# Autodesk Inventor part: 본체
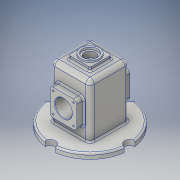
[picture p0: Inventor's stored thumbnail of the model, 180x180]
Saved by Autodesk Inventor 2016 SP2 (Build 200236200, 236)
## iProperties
Created: 2018-07
Part Number: 본체
Material: 알루미늄 6061
Document SubType Name: Modeling
Designer: Administrator
Density: 2.7 g/cm^3
Appearance: 알루미늄 - 평지
Mass: 905.953 g
Surface Area: 1026.21 cm^2
Volume: 335.538 cm^3
Author: Administrator
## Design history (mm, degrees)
sketch "스케치11"
  geometry: L1 (-37, -37)-(37, -37); L2 (37, -37)-(37, 37); L3 (37, 37)-(-37, 37); L4 (-37, 37)-(-37, -37); L5 (-37, -37)-(37, 37); L6 (37, -37)-(-37, 37); 1 further point
  constraints: 12 end point, 2 midpoint, 2 parallel, 1 horizontal, 1 perpendicular
  dimensions: "d36" = 74 distance of L3.end L2.end; "d37" = 74 distance of L2.end L1.end
extrude "돌출9" new body sketch "스케치11" distance "d38" = 100; taper "d39" = 0 deg
feature "쉘2" dims "d40" = 5
sketch "스케치12"
  geometry: L1 (20, -20)-(-20, -20); L2 (-20, -20)-(-20, 20); L3 (-20, 20)-(20, 20); L4 (20, 20)-(20, -20); L5 (20, -20)-(-20, 20); L6 (-20, -20)-(20, 20); 1 further point
  constraints: 12 end point, 2 midpoint, 2 parallel, 1 horizontal, 1 perpendicular
  dimensions: "d41" = 40 distance of L2.end L3.end; "d42" = 40 distance of L1.end L2.end
extrude "돌출10" join sketch "스케치12" distance "d43" = 7; taper "d44" = 0 deg
sketch "스케치14"
  geometry: A1 r 75 centre (0, 0) between (74.333, 9.978) and (9.978, 74.333); A2 r 10 centre (75, 0) between (74.333, -9.978) and (74.333, 9.978); A3 r 10 centre (0, -75) between (-9.978, -74.333) and (9.978, -74.333); A4 r 10 centre (-75, 0) between (-74.333, -9.978) and (-74.333, 9.978); A5 r 10 centre (0, 75) between (-9.978, 74.333) and (9.978, 74.333); A6 r 75 centre (0, 0) between (74.333, -9.978) and (74.333, 9.978); A7 r 75 centre (0, 0) between (-9.978, -74.333) and (9.978, -74.333); A8 r 75 centre (0, 0) between (9.978, -74.333) and (74.333, -9.978); A9 r 75 centre (0, 0) between (-74.333, -9.978) and (-9.978, -74.333); A10 r 75 centre (0, 0) between (-74.333, 9.978) and (-74.333, -9.978); A11 r 75 centre (0, 0) between (-9.978, 74.333) and (-74.333, 9.978); A12 r 75 centre (0, 0) between (9.978, 74.333) and (-9.978, 74.333); 1 further point
  constraints: 38 point on circle, 12 centre point, 2 horizontal alignment, 2 vertical alignment, 1 coincident
  dimensions: "d48" = 150 diameter of A1; "d49" = 20 diameter of A2; "d50" = 20 diameter of A3; "d51" = 20 diameter of A4; "d52" = 20 diameter of A5
extrude "돌출12" join sketch "스케치14" distance "d53" = 10; taper "d54" = 0 deg
sketch "스케치15"
  geometry: L1 (-37.333, -110)-(27.022, -110) reference; L2 (62, -30)-(12, -30); L3 (12, -30)-(12, -80); L4 (12, -80)-(62, -80); L5 (62, -80)-(62, -30); L6 (62, -30)-(12, -80); L7 (12, -30)-(62, -80); 2 further points
  constraints: 12 end point, 2 midpoint, 2 parallel, 1 horizontal, 1 perpendicular, 1 vertical alignment
  dimensions: "d55" = 50 distance of L4.end L3.end; "d56" = 50 distance of L3.end L2.end; "d57" = 55 distance from line of L1 point (37, -55)
extrude "돌출13" join sketch "스케치15" distance "d58" = 13; taper "d59" = 0 deg
sketch "스케치16"
  geometry: L1 (-37.333, -110)-(27.022, -110) reference; L2 (62, -30)-(12, -30); L3 (12, -30)-(12, -80); L4 (12, -80)-(62, -80); L5 (62, -80)-(62, -30); L6 (62, -30)-(12, -80); L7 (12, -30)-(62, -80); 3 further points
  constraints: 12 end point, 3 midpoint, 2 parallel, 1 horizontal, 1 perpendicular, 1 vertical alignment
  dimensions: "d60" = 50 distance of L4.end L3.end; "d61" = 50 distance of L3.end L2.end; "d62" = 55 distance from line of L1 point (37, -55)
extrude "돌출14" join sketch "스케치16" distance "d63" = 13; taper "d64" = 0 deg
sketch "스케치17"
  geometry: L1 (70, 37)-(70, 50) reference; L2 (5, 32)-(95, 32) reference; L3 (70, -37)-(70, -50) reference; L4 (5, -32)-(95, -32) reference; L5 (70, 50)-(20, 50) reference; L6 (20, -50)-(70, -50) reference; L7 (45, 32)-(45, -32); L8 (0, -9.978)-(0, -74.333) reference; L9 (0, -74.333)-(-10, -74.333) reference; L10 (-10, -9.978)-(-10, -74.333) reference; L11 (0, -9.978)-(-10, -9.978) reference; L12 (45, 32)-(70, 32); L13 (70, 32)-(67.452, 25); L14 (67.452, 25)-(45, 25); L15 (45, 32)-(45, 25); 1 further point
  constraints: 10 end point, 4 point on line, 2 perpendicular, 1 collinear, 1 vertical alignment
  dimensions: "d68" = 55 distance between parallel lines of L10 L7; "d69" = 7 vertical distance of L13.end L12.end; "d70" = 110 deg angle of L2 L13
revolve "회전1" sketch "스케치17" stored, may be unused: angle "d71" = 90 deg
sketch "스케치18"
  geometry: L1 (-37.333, -110)-(27.022, -110) reference; C1 r 16 at (37, -55); 1 further point
  constraints: 1 centre point, 1 vertical alignment
  dimensions: "d72" = 32 diameter of C1; "d73" = 55 distance from line of L1 C1.centre
extrude "돌출15" cut sketch "스케치18" stored distance "d74" = 13; taper "d75" = 0 deg
sketch "스케치19"
  geometry: L1 (32, 32)-(-32, 32); L2 (-32, 32)-(-32, -32); L3 (-32, -32)-(32, -32); L4 (32, -32)-(32, 32); L5 (32, 32)-(-32, -32); L6 (-32, 32)-(32, -32); 1 further point
  constraints: 12 end point, 2 midpoint, 2 parallel, 1 horizontal, 1 perpendicular
  dimensions: "d76" = 64 distance of L3.end L2.end; "d77" = 64 distance of L2.end L1.end
extrude "돌출16" cut sketch "스케치19" stored distance "d78" = 13; taper "d79" = 0 deg
fillet "모깎기1" dims "d83" = 6
sketch "스케치22"
  geometry: L1 (62, -36)-(62, -74) reference; L2 (56, -80)-(18, -80) reference; L3 (12, -74)-(12, -36) reference; L4 (18, -30)-(56, -30) reference; L5 (0, -100)-(74, -100) reference; L6 (74, -100)-(74, 0) reference; L7 (0, 0)-(74, 0) reference; L8 (0, -100)-(0, 0) reference; A1 r 6 centre (56, -74) between (56, -80) and (62, -74) reference; A2 r 6 centre (18, -74) between (12, -74) and (18, -80) reference; A3 r 6 centre (18, -36) between (18, -30) and (12, -36) reference; A4 r 6 centre (56, -36) between (62, -36) and (56, -30) reference; 5 further points
  constraints: 4 coincident
hole "구멍1" sketch "스케치22" at (18, -36), (56, -36), (56, -74), (18, -74) diameter "d84" = 3.242; stored, may be unused: countersink angle "d88" = 90 deg, drill point angle "d90" = 118 deg; dims "d85" = 8, "d86" = 4, "d87" = 2, "d89" = 10
fillet "모깎기2" dims "d91" = 8
chamfer "모따기1" distance "d92" = 1; stored, may be unused: second distance "d93" = 2, angle "d94" = 45 deg
fillet "모깎기3" dims "d95" = 3
fillet "모깎기4" dims "d96" = 3
fillet "모깎기5" dims "d97" = 3
fillet "모깎기6" dims "d98" = 3
sketch "스케치23"
  geometry: C1 r 17.5 at (0, 0); 1 further point
  constraints: 1 centre point, 1 coincident
  dimensions: "d99" = 35 diameter of C1
extrude "돌출18" join sketch "스케치23" distance "d100" = 3; taper "d101" = 0 deg
sketch "스케치24"
  geometry: C1 r 14 at (0, 0); 1 further point
  constraints: 1 centre point, 1 coincident
  dimensions: "d102" = 28 diameter of C1
extrude "돌출19" cut sketch "스케치24" distance "d103" = 4; taper "d104" = 0 deg
sketch "스케치25"
  geometry: C1 r 10.5 at (0, 0); 1 further point
  constraints: 1 centre point, 1 coincident
  dimensions: "d105" = 21 diameter of C1
extrude "돌출20" cut sketch "스케치25" stored distance "d106" = 4; taper "d107" = 0 deg
sketch "스케치26"
  geometry: L1 (66, -89)-(66, 0) reference; L2 (46.5, 18)-(11.5, 18) reference; 2 further points
  constraints: 1 other
  dimensions: "d108" = 30 distance from line of L2 point (29, -12); "d109" = 37 distance from line of L1 point (29, -12)
feature "엠보싱1" sketch "스케치26" dims "d36" = 74, "d37" = 74, "d49" = 20, "d110" = 0.5, "d111" = 0
node "솔리드2"
mirror "대칭1"
mirror "대칭2"
node "투영된 루프6"
node "투영된 루프7"
